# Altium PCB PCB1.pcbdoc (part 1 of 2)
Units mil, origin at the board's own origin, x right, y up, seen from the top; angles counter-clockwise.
Board outline 2817.44 x 1578.14 mil, 2 copper layers (Top Layer, Bottom Layer); 132 components, 113 nets, 538 pads, 285 vias.
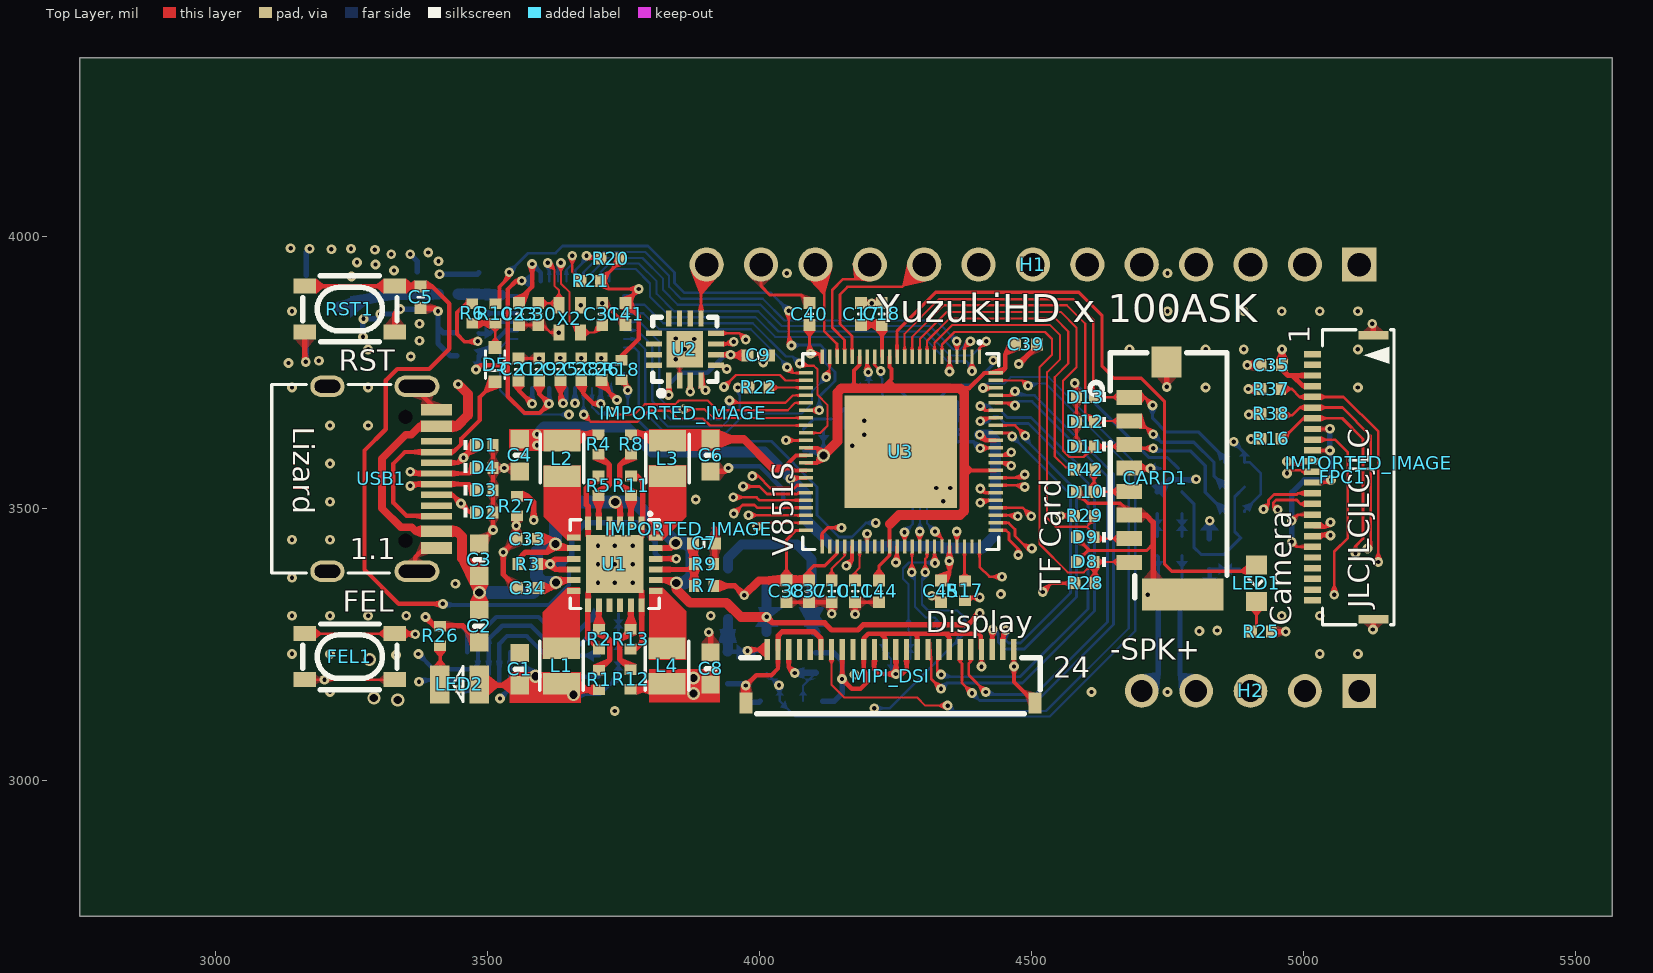
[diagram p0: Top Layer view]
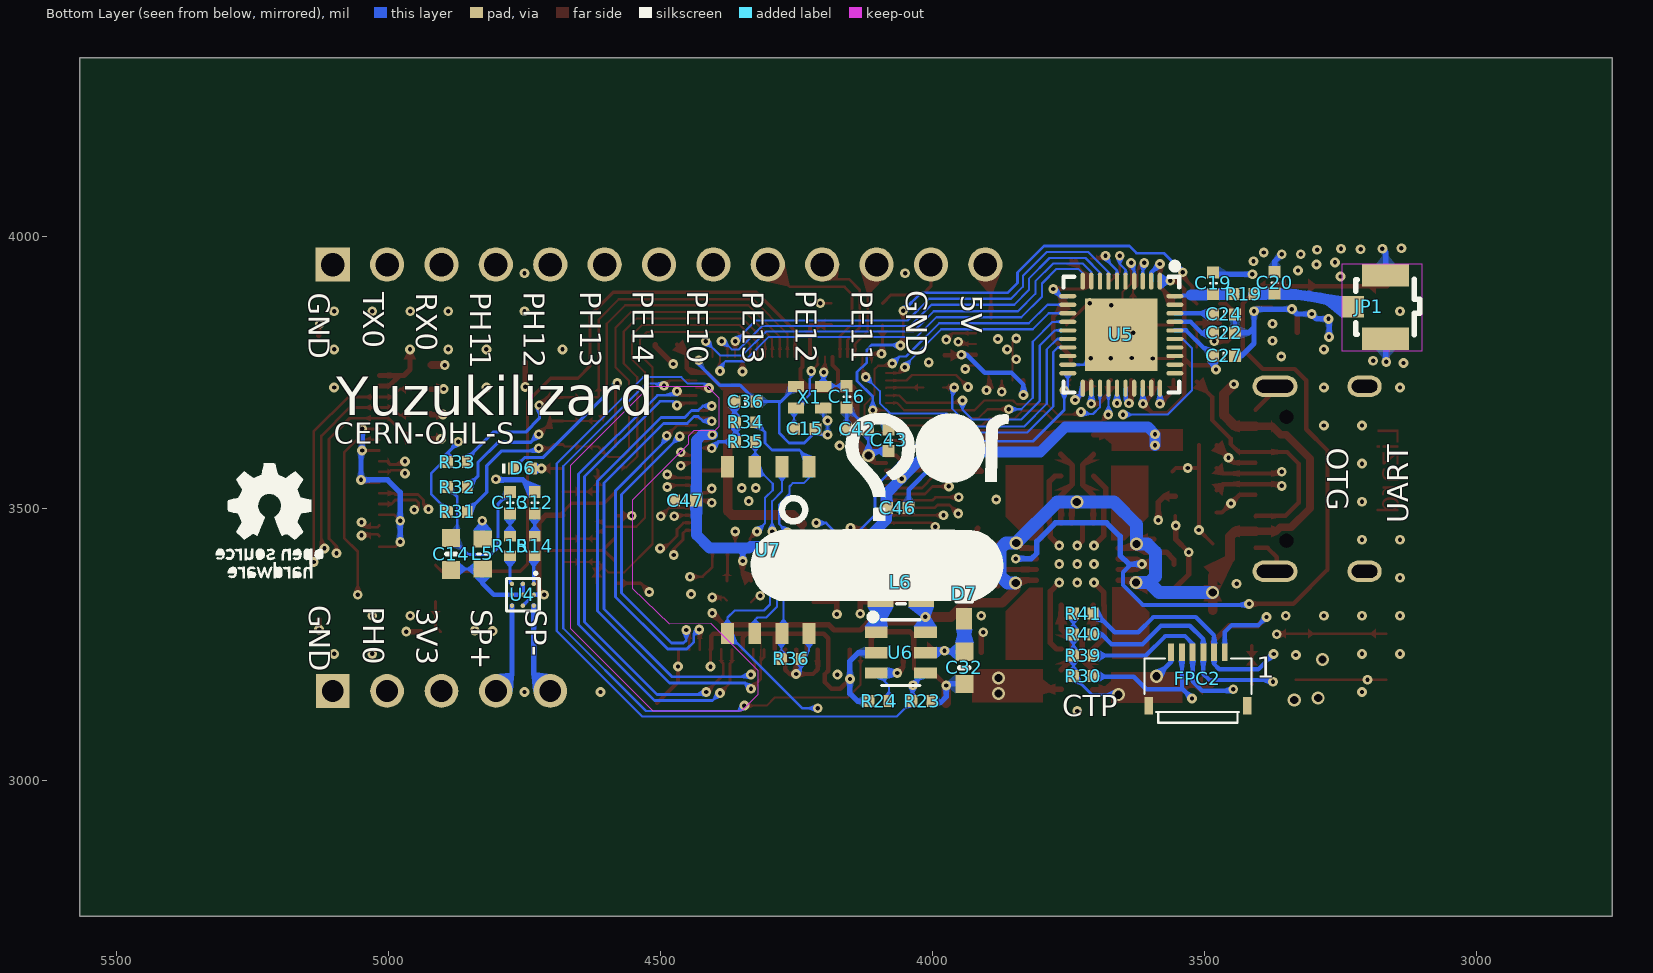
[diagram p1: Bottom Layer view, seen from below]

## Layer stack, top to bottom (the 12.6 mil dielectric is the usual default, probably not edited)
Top Solder: solder mask 0.4, Solder Resist, Dk 3.5
Top Layer: signal copper 1.4
Dielectric 1: dielectric 12.6, FR-4, Dk 4.8
Bottom Layer: signal copper 1.4
Bottom Solder: solder mask 0.4, Solder Resist, Dk 3.5

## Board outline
5567.44,2750 2750,2750 2750,4328.14 5567.44,4328.14

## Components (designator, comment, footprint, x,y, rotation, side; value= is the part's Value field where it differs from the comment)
C1 "CAP_0603" "C0603 NSK" 3558.67,3204.23 r270 top
C2 "CAP_0603" "C0603 NSK" 3484.5,3283.13 r90 top
C3 "CAP_0603" "C0603 NSK" 3484.5,3405.13 r270 top
C4 "CAP_0603" "C0603 NSK" 3558.67,3597.28 r90 top
C5 "100nF" C0402-NSK 3376.5,3888.14 r270 top
C6 "CAP_0603" "C0603 NSK" 3909.67,3597.28 r90 top
C7 "100nF" C0402-NSK 3897.67,3435.26 r180 top
C8 "CAP_0603" "C0603 NSK" 3909.67,3205.26 r270 top
C9 "100nF" C0402-NSK 3997.5,3781.13 r180 top
C10 "2.2uF" C0402-NSK 4132.5,3347.13 r270 top
C11 "470nF" C0402-NSK 4175.5,3347.13 r270 top
C12 "100nF" C0402-NSK 4731.05,3510.31 r270 bottom
C13 "100nF" C0402-NSK 4776.36,3510.31 r270 bottom
C14 "CAP_0603" "C0603 NSK" 4884.85,3415.88 r270 bottom
C15 "22pF" C0402-NSK 4234.5,3646.05 r180 bottom
C16 "22pF" C0402-NSK 4157.5,3705.05 r270 bottom
C17 "2.2uF" C0402-NSK 4186.3,3857.06 r270 top
C18 "100nF" C0402-NSK 4224.43,3857.34 r270 top
C19 "CAP_0402" C0402-NSK 3483.64,3913.49 r270 bottom
C20 "CAP_0402" C0402-NSK 3370.64,3914.49 r270 bottom
C21 "CAP_0402" C0402-NSK 3556.67,3755.24 r90 top
C22 "CAP_0402" C0402-NSK 3463.46,3822.36 r180 bottom
C23 "CAP_0402" C0402-NSK 3557.85,3856.99 r270 top
C24 "CAP_0402" C0402-NSK 3463.46,3856.36 r180 bottom
C25 "CAP_0402" C0402-NSK 3633.95,3755.7 r90 top
C26 "CAP_0402" C0402-NSK 3708.95,3755.7 r90 top
C27 "CAP_0402" C0402-NSK 3463.5,3780.13 r180 bottom
C28 "CAP_0402" C0402-NSK 3671.95,3755.7 r90 top
C29 "CAP_0402" C0402-NSK 3594.67,3755.24 r90 top
C30 "22pF" C0402-NSK 3592.85,3857 r270 top
C31 "22pF" C0402-NSK 3710.5,3857.13 r90 top
C32 "CAP_0603" "C0603 NSK" 3940.92,3206.54 r90 bottom
C33 "1uF" C0402-NSK 3572.67,3443.26 r180 top
C34 "1uF" C0402-NSK 3573.67,3353.26 r180 top
C35 "100nF" C0402-NSK 4940.5,3763.13 r0 top
C36 "100nF" C0402-NSK 4343.5,3696.13 r0 bottom
C37 "100nF" C0402-NSK 4090.5,3347.13 r90 top
C38 "100nF" C0402-NSK 4049.5,3347.13 r90 top
C39 "100nF" C0402-NSK 4489.5,3801.13 r0 top
C40 "100nF" C0402-NSK 4091.5,3857.13 r270 top
C41 "100nF" C0402-NSK 3753.5,3857.13 r90 top
C42 "100nF" C0402-NSK 4138.5,3645.13 r180 bottom
C43 "100nF" C0402-NSK 4080.5,3625.13 r270 bottom
C44 "100nF" C0402-NSK 4219.5,3347.13 r90 top
C45 "100nF" C0402-NSK 4333.5,3347.13 r90 top
C46 "100nF" C0402-NSK 4063.5,3500.13 r0 bottom
C47 "100nF" C0402-NSK 4454.5,3514.13 r180 bottom
CARD1 "TF-021B-H265" TF-SMD_TF-021B-H265 4728.5,3555.13 r90 top
D1 "0402ESDA-05N" D0402 3493.5,3616.13 r0 top
D2 "0402ESDA-05N" D0402 3493.5,3492.13 r0 top
D3 "0402ESDA-05N" D0402 3493.5,3533.13 r0 top
D4 "0402ESDA-05N" D0402 3493.5,3574.13 r0 top
D5 "1N5819-SOD523" SOD-523_L1.2-W0.8-LS1.6-FD 3513.5,3764.13 r270 top
D6 "0402ESDA-05N" D0402 4753.5,3573.13 r180 bottom
D7 "B5819WS_C22624" SOD-323_L1.8-W1.3-LS2.5-RD 3941.5,3343.13 r90 bottom
D8 "0402ESDA-05N" D0402 4598.84,3401.36 r180 top
D9 "0402ESDA-05N" D0402 4598.84,3446.73 r180 top
D10 "0402ESDA-05N" D0402 4598.5,3530.13 r180 top
D11 "0402ESDA-05N" D0402 4598.84,3613.47 r180 top
D12 "0402ESDA-05N" D0402 4598.84,3658.84 r180 top
D13 "0402ESDA-05N" D0402 4598.84,3704.21 r180 top
FEL1 "PTS810SJM250SMTRLFS" KEY-SMD_4P-L4.2-W3.2-P2.20-LS4.6 3246.5,3227.13 r0 top
FPC1 "F0502-B-24-10G-R" FPC-SMD_F0502-B-24-10G-R 5072.5,3557.13 r90 top
FPC2 "FH19C-6S-0.5SH(10)" FPC-SMD_FH19C-6S-0.5SH 3511.5,3186.13 r180 bottom
H1 "HDR-F_2.54_1x13P" HDR-TH_13P-P2.54-V-F 4502.5,3948.13 r180 top
H2 "HDR-F_2.54_1x5P" HDR-TH_5P-P2.54-V-F 4902.5,3164.13 r180 top
IMPORTED_IMAGE "IMPORTED_IMAGE" IMPORTED_IMAGE 3859.5,3675.13 r0 top
IMPORTED_IMAGE "IMPORTED_IMAGE" IMPORTED_IMAGE 3869.57,3461.13 r0 top
IMPORTED_IMAGE "IMPORTED_IMAGE" IMPORTED_IMAGE 5119.5,3583.13 r0 top
JP1 "U.FL-R-SMT-1(80)" RF-SMD_FRF05002-JSS103M 3196.5,3870.13 r270 bottom
L1 "2.2uH" IND-SMD_L2.0-W1.6 3635.67,3210.26 r270 top
L2 "2.2uH" IND-SMD_L2.0-W1.6 3636.67,3591.26 r90 top
L3 "2.2uH" IND-SMD_L2.0-W1.6 3830.67,3591.26 r90 top
L4 "2.2uH" IND-SMD_L2.0-W1.6 3829.67,3210.26 r270 top
L5 "UPZ1608E101-3R0TF" "L0603 NSK" 4826.85,3415.88 r90 bottom
L6 "WPN252012H4R7MT" IND-SMD_L2.5-W2.0_SWPA252010S1R0MT 4057.92,3363.54 r0 bottom
LED1 "LED_0603-R" "LED0603 NSK" 4913.5,3362.13 r90 top
LED2 "LED_0807-RGB" RGBLED_0807 3448.5,3176.13 r180 top
MIPI_DSI "FH34SRJ-24S-0.5SH(50)" FFC-SMD_24P-P0.50_FH34SRJ-24S-0.5SH 4240.5,3191.13 r0 top
R1 "680K" R0402-NSK_2 3704.67,3184.26 r270 top
R2 "150K" R0402-NSK_2 3704.67,3259.26 r270 top
R3 "10K" R0402-NSK_2 3573.67,3397.26 r180 top
R4 "300K" R0402-NSK_2 3703.67,3617.26 r90 top
R5 "150K" R0402-NSK_2 3703.67,3541.26 r90 top
R6 "Res_0402" R0402-NSK_2 3471.5,3858.13 r90 top
R7 "100K" R0402-NSK_2 3897.67,3357.26 r0 top
R8 "150K" R0402-NSK_2 3763.67,3617.26 r90 top
R9 "100K" R0402-NSK_2 3897.67,3397.26 r180 top
R10 "Res_0402" R0402-NSK_2 3513.83,3857.92 r270 top
R11 "100K" R0402-NSK_2 3763.67,3541.26 r90 top
R12 "75K" R0402-NSK_2 3762.67,3185.26 r270 top
R13 "150K" R0402-NSK_2 3762.67,3259.26 r270 top
R14 "100K" R0402-NSK_2 4731.05,3430.47 r270 bottom
R15 "100K" R0402-NSK_2 4776.36,3430.47 r270 bottom
R16 "2K" R0402-NSK_2 4940.34,3627.81 r0 top
R17 "33" R0402-NSK_2 4377.5,3348.13 r270 top
R18 "47K" R0402-NSK_2 3745.67,3754.24 r90 top
R19 "Res_0402" R0402-NSK_2 3427.25,3893.8 r180 bottom
R20 "47K" R0402-NSK_2 3726.5,3959.13 r0 top
R21 "47K" R0402-NSK_2 3689.5,3918.13 r0 top
R22 "33" R0402-NSK_2 3998.5,3722.13 r0 top
R23 "Res_0402" R0402-NSK_2 4018.92,3145.54 r0 bottom
R24 "Res_0402" R0402-NSK_2 4097.92,3145.53 r180 bottom
R25 "2K" R0402-NSK_2 4922.5,3273.13 r0 top
R26 "2K" R0402-NSK_2 3412.5,3265.13 r90 top
R27 "100K" R0402-NSK_2 3553.5,3504.13 r90 top
R28 "47K" R0402-NSK_2 4598.5,3362.13 r180 top
R29 "47K" R0402-NSK_2 4597.5,3486.13 r180 top
R30 "10K" R0402-NSK_2 3722.5,3191.13 r180 bottom
R31 "47K" R0402-NSK_2 4873.34,3493.31 r0 bottom
R32 "47K" R0402-NSK_2 4873.34,3539 r0 bottom
R33 "47K" R0402-NSK_2 4873.34,3584.68 r0 bottom
R34 "Res_0402" R0402-NSK_2 4343.5,3658.13 r0 bottom
R35 "Res_0402" R0402-NSK_2 4343.5,3622.14 r0 bottom
R36 "Res_0402" R0402-NSK_2 4259.5,3223.13 r180 bottom
R37 "10K" R0402-NSK_2 4940.34,3719.18 r0 top
R38 "2K" R0402-NSK_2 4940.34,3673.49 r0 top
R39 "2K" R0402-NSK_2 3722.5,3229.13 r180 bottom
R40 "2K" R0402-NSK_2 3722.5,3268.13 r180 bottom
R41 "10K" R0402-NSK_2 3722.5,3306.13 r180 bottom
R42 "33" R0402-NSK_2 4598.5,3571.13 r0 top
RST1 "PTS810SJM250SMTRLFS" KEY-SMD_4P-L4.2-W3.2-P2.20-LS4.6 3246.5,3866.13 r180 top
U1 "EA3059" QFN-24_L4.0-W4.0-P0.50-TL-EP2.7 3733.67,3397.26 r270 top
U2 "CH343P" TQFN-16_L3.0-W3.0-P0.50-BL-EP1.7 3862.5,3792.13 r0 top
U3 "V851S" QFN-88_L9.0-W9.0-P0.35-BL-EP5.26 4259.5,3604.13 r180 top
U4 "AW8010AFCR" FC-9_L1.5-W1.5-R3-C3-P0.50-BL 4752.85,3340.88 r0 bottom
U5 "XR829" QFN-40_L5.0-W5.0-P0.40-BL-EP3.4 3652.5,3819.13 r0 bottom
U6 "RY3730" SOT-23-6_L2.9-W1.6-P0.95-LS2.8-BL 4057.92,3234.54 r270 bottom
U7 "W25Q128JVSIQ" SOIC-8_L5.3-W5.3-P1.27-LS8.0-BL_1 4301.5,3428.13 r0 bottom
USB1 "TYPEC-304-BCP16" USB-C-SMD_TYPEC-304-BCP16-1 3305.5,3554.13 r270 top
X1 "24MHz" OSC-SMD_4P-L2.0-W1.6-BL 4225.5,3704.05 r0 bottom
X2 "40MHz" OSC-SMD_4P-L2.0-W1.6-BL 3650.85,3847.99 r270 top

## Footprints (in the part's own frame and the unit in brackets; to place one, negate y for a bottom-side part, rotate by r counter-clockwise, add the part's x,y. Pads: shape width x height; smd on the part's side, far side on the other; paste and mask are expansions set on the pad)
C0402-NSK [mil]
  rect 22x22 smd: 1(-19.99,0) 2(20.01,0)
  silkscreen extent 0,-5 0,6
"C0603 NSK" [mm]
  rect 0.85x0.85 smd: 1(-0.75,0) 2(0.75,0)
  silkscreen extent 0,-0.21 0,0.21
D0402 [mil]
  rect 19.89x21.68 smd: 1(-16.4,0) 2(16.4,0)
  silkscreen extent -37,-9 -31,9
FC-9_L1.5-W1.5-R3-C3-P0.50-BL [mil]
  round 8.19 smd: A1(-20,-20) A2(-20,0) A3(-20,20) B1(0,-20) B2(0,0) B3(0,20) C1(20,-20) C2(20,0) C3(20,20)
  silkscreen extent -30,-41 30,30
FFC-SMD_24P-P0.50_FH34SRJ-24S-0.5SH [mil]
  rect 9.8x39.4 smd: 1(226.4,49.2) 2(206.7,49.2) 3(187,49.2) 4(167.3,49.2) 5(147.6,49.2) 6(128,49.2) 7(108.3,49.2) 8(88.6,49.2) 9(68.9,49.2) 10(49.2,49.2) 11(29.5,49.2) 12(9.9,49.2) 13(-9.8,49.2) 14(-29.5,49.2) 15(-49.2,49.2) 16(-68.9,49.2) 17(-88.6,49.2) 18(-108.3,49.2) 19(-127.9,49.2) 20(-147.6,49.2) 21(-167.3,49.2) 22(-187,49.2) 23(-206.7,49.2) 24(-226.4,49.2)
  rect 23.6x39.4 smd: 25(-265.7,-49.2) 26(265.8,-49.2)
  silkscreen extent -276,-69 276,34
FPC-SMD_F0502-B-24-10G-R [mm]
  rect 0.3x0.8 smd: 1(5.75,1.418) 2(5.25,1.418) 3(4.75,1.418) 4(4.25,1.418) 5(3.75,1.418) 6(3.25,1.418) 7(2.75,1.418) 8(2.25,1.418) 9(1.75,1.418) 10(1.25,1.418) 11(0.75,1.418) 12(0.25,1.418) 13(-0.25,1.418) 14(-0.75,1.418) 15(-1.25,1.418) 16(-1.75,1.418) 17(-2.25,1.418) 18(-2.75,1.418) 19(-3.25,1.418) 20(-3.75,1.418) 21(-4.25,1.418) 22(-4.75,1.418) 23(-5.25,1.418) 24(-5.75,1.418)
  rect 0.4x1.4 smd: 25(-6.635,-1.418) 26(6.635,-1.418)
  silkscreen extent -6.89,-2.39 6.89,0.96
FPC-SMD_FH19C-6S-0.5SH [mil]
  rect 11x31.5 smd: 1(-49.2,49.2) 2(-29.5,49.2) 3(-9.9,49.2) 4(9.8,49.2) 5(29.5,49.2) 6(49.2,49.2)
  rect 15.7x31.5 smd: 7(90.6,-49.2) 8(-90.6,-49.2)
  silkscreen extent -98,-81 98,37
HDR-TH_5P-P2.54-V-F [mil]
  rect 62x62 hole 40.16: 1(-200,0)
  round 62 hole 40.16: 2(-100,0) 3(0,0) 4(100,0) 5(200,0)
HDR-TH_13P-P2.54-V-F [mil]
  rect 63x63 hole 43.3: 1(-600,0)
  round 63 hole 43.3: 2(-500,0) 3(-400,0) 4(-300,0) 5(-200,0) 6(-100,0) 7(0,0) 8(100,0) 9(200,0) 10(300,0) 11(400,0) 12(500,0) 13(600,0)
IMPORTED_IMAGE [mil]
IND-SMD_L2.0-W1.6 [mm]
  rect 1x1.72 smd: 1(0.828,0) 2(-0.828,0)
  silkscreen extent -1.14,-1.02 1.14,1.02
IND-SMD_L2.5-W2.0_SWPA252010S1R0MT [mil]
  rect 47.2x90.6 smd: 1(-37.4,0) 2(37.4,0)
  silkscreen extent -8,-40 8,39
KEY-SMD_4P-L4.2-W3.2-P2.20-LS4.6 [mil]
  rect 41.3x27.6 smd: 1(-82.7,42.3) 2(82.7,42.3) 3(-82.7,-42.3) 4(82.7,-42.3)
  silkscreen extent -87,-61 87,60
"L0603 NSK" [mm]
  rect 0.8x0.864 smd: 1(0.7,0) 2(-0.7,0)
  silkscreen extent 0,-0.25 0,0.24
"LED0603 NSK" [mm]
  rect 0.9x1 smd: 1(-0.85,0) 2(0.85,0)
  silkscreen extent -0.17,-0.36 0.2,0.37
OSC-SMD_4P-L2.0-W1.6-BL [mil]
  rect 30x20 smd: 1(-25,-20) 2(25,-20) 3(25,20) 4(-25,20)
QFN-24_L4.0-W4.0-P0.50-TL-EP2.7 [mm]
  rect 0.633x0.28 smd: 1(-1.912,1.25) 2(-1.912,0.75) 3(-1.912,0.25) 4(-1.912,-0.25) 5(-1.912,-0.75) 6(-1.912,-1.25) 13(1.912,-1.25) 14(1.912,-0.75) 15(1.912,-0.25) 16(1.912,0.25) 17(1.912,0.75) 18(1.912,1.25)
  rect 0.28x0.633 smd: 7(-1.25,-1.912) 8(-0.75,-1.912) 9(-0.25,-1.912) 10(0.25,-1.912) 11(0.75,-1.912) 12(1.25,-1.912) 19(1.25,1.912) 20(0.75,1.912) 21(0.25,1.912) 22(-0.25,1.912) 23(-0.75,1.912) 24(-1.25,1.912)
  rect 2.7x2.7 smd: 25(0,0)
  silkscreen extent -2.42,-2.08 2.08,2.08
QFN-40_L5.0-W5.0-P0.40-BL-EP3.4 [mm]
  oval 0.2x0.8 smd: 1(-1.8,-2.499) 2(-1.4,-2.499) 3(-1,-2.499) 4(-0.6,-2.499) 5(-0.2,-2.499) 6(0.2,-2.499) 7(0.6,-2.499) 8(1,-2.499) 9(1.4,-2.499) 10(1.8,-2.499) 21(1.8,2.499) 22(1.4,2.499) 23(1,2.499) 24(0.6,2.499) 25(0.2,2.499) 26(-0.2,2.499) 27(-0.6,2.499) 28(-1,2.499) 29(-1.4,2.499) 30(-1.8,2.499)
  oval 0.8x0.2 smd: 11(2.499,-1.8) 12(2.499,-1.4) 13(2.499,-1) 14(2.499,-0.6) 15(2.499,-0.2) 16(2.499,0.2) 17(2.499,0.6) 18(2.499,1) 19(2.499,1.4) 20(2.499,1.8) 31(-2.499,1.8) 32(-2.499,1.4) 33(-2.499,1) 34(-2.499,0.6) 35(-2.499,0.2) 36(-2.499,-0.2) 37(-2.499,-0.6) 38(-2.499,-1) 39(-2.499,-1.4) 40(-2.499,-1.8)
  rect 3.4x3.4 smd: 41(0,0)
  silkscreen extent -2.7,-3.35 2.7,2.7
QFN-88_L9.0-W9.0-P0.35-BL-EP5.26 [mm]
  rect 0.16x0.665 smd: 1(-3.675,-4.433) 2(-3.325,-4.433) 3(-2.975,-4.433) 4(-2.625,-4.433) 5(-2.275,-4.433) 6(-1.925,-4.433) 7(-1.575,-4.433) 8(-1.225,-4.433) 9(-0.875,-4.433) 10(-0.525,-4.433) 11(-0.175,-4.433) 12(0.175,-4.433) 13(0.525,-4.433) 14(0.875,-4.433) 15(1.225,-4.433) 16(1.575,-4.433) 17(1.925,-4.433) 18(2.275,-4.433) 19(2.625,-4.433) 20(2.975,-4.433) 21(3.325,-4.433) 22(3.675,-4.433) 45(3.675,4.433) 46(3.325,4.433) 47(2.975,4.433) 48(2.625,4.433) 49(2.275,4.433) 50(1.925,4.433) 51(1.575,4.433) 52(1.225,4.433) 53(0.875,4.433) 54(0.525,4.433) 55(0.175,4.433) 56(-0.175,4.433) 57(-0.525,4.433) 58(-0.875,4.433) 59(-1.225,4.433) 60(-1.575,4.433) 61(-1.925,4.433) 62(-2.275,4.433) 63(-2.625,4.433) 64(-2.975,4.433) 65(-3.325,4.433) 66(-3.675,4.433)
  rect 0.665x0.16 smd: 23(4.433,-3.675) 24(4.433,-3.325) 25(4.433,-2.975) 26(4.433,-2.625) 27(4.433,-2.275) 28(4.433,-1.925) 29(4.433,-1.575) 30(4.433,-1.225) 31(4.433,-0.875) 32(4.433,-0.525) 33(4.433,-0.175) 34(4.433,0.175) 35(4.433,0.525) 36(4.433,0.875) 37(4.433,1.225) 38(4.433,1.575) 39(4.433,1.925) 40(4.433,2.275) 41(4.433,2.625) 42(4.433,2.975) 43(4.433,3.325) 44(4.433,3.675) 67(-4.433,3.675) 68(-4.433,3.325) 69(-4.433,2.975) 70(-4.433,2.625) 71(-4.433,2.275) 72(-4.433,1.925) 73(-4.433,1.575) 74(-4.433,1.225) 75(-4.433,0.875) 76(-4.433,0.525) 77(-4.433,0.175) 78(-4.433,-0.175) 79(-4.433,-0.525) 80(-4.433,-0.875) 81(-4.433,-1.225) 82(-4.433,-1.575) 83(-4.433,-1.925) 84(-4.433,-2.275) 85(-4.433,-2.625) 86(-4.433,-2.975) 87(-4.433,-3.325) 88(-4.433,-3.675)
  rect 5.26x5.26 smd: 89(0,0)
  silkscreen extent -4.58,-5.17 4.58,4.58
R0402-NSK_2 [mil]
  rect 19.68x22 smd: 1(-18,0) 2(18,0)
RF-SMD_FRF05002-JSS103M [mm]
  rect 1x1.05 smd: 1(0,-0.762)
  rect 1.05x2.2 smd: 2(-1.475,0.762) 3(1.475,0.762)
  silkscreen extent -1.3,-0.63 1.3,2.35
RGBLED_0807 [mil]
  rect 35.83x70 smd: 1(-36,0) 2(37,0)
  silkscreen extent -6,-33 12,32
SOD-323_L1.8-W1.3-LS2.5-RD [mil]
  rect 39.4x29.5 smd: 1(-46.2,0) 2(46.2,0)
  silkscreen extent -15,-15 -15,15
SOD-523_L1.2-W0.8-LS1.6-FD [mil]
  rect 23.6x23.6 smd: 1(-31.5,0) 2(31.5,0)
  silkscreen extent -26,-18 26,18
SOIC-8_L5.3-W5.3-P1.27-LS8.0-BL_1 [mil]
  rect 23.6x39.4 smd: 1(-75,-148.5) 2(-25,-148.5) 3(25,-148.5) 4(75,-148.5) 5(75,158.5) 6(25,158.5) 7(-25,158.5) 8(-75,158.5)
  silkscreen extent -68,-90 -25,-48
SOT-23-6_L2.9-W1.6-P0.95-LS2.8-BL [mil]
  rect 20.9x42.2 smd: 1(-37.4,-45.2) 2(0,-45.2) 3(37.4,-45.2) 4(37.4,45.2) 5(0,45.2) 6(-37.4,45.2)
  silkscreen extent -72,-57 61,35
TF-SMD_TF-021B-H265 [mil]
  rect 27.6x47.2 smd: 1(148.6,49.2) 2(105.3,49.2) 3(62,49.2) 4(18.7,49.2) 5(-24.6,49.2) 6(-67.9,49.2) 7(-111.2,49.2) 8(-154.5,49.2)
  rect 59.1x149.6 smd: 9(-213.6,-49.2)
  rect 57.1x55.1 smd: 10(213.6,-19.7)
  silkscreen extent -220,-131 230,121
TQFN-16_L3.0-W3.0-P0.50-BL-EP1.7 [mm]
  rect 0.25x0.75 smd: 1(-0.748,-1.45) 2(-0.249,-1.45) 3(0.252,-1.45) 4(0.751,-1.45) 9(0.75,1.45) 10(0.25,1.45) 11(-0.25,1.45) 12(-0.749,1.45)
  rect 0.75x0.25 smd: 5(1.45,-0.75) 6(1.45,-0.25) 7(1.45,0.25) 8(1.45,0.75) 13(-1.45,0.75) 14(-1.45,0.25) 15(-1.45,-0.25) 16(-1.45,-0.75)
  rect 1.7x1.7 smd: 17(0,0)
  silkscreen extent -1.5,-2.17 1.5,1.5
USB-C-SMD_TYPEC-304-BCP16-1 [mil]
  oval 39.4x82.7 hole 23.6 slot 66.9 at 90 deg: 12(-170.1,64.3) 13(170.1,64.3)
  oval 39.4x63 hole 23.6 slot 47.2 at 90 deg: 14(-170.1,-100.3) 15(170.1,-100.3)
  rect 21.7x57.1 smd: A1B12(-127,100.3) A4B9(-96.5,100.3) B1A12(127,100.3) B4A9(96.5,100.3)
  rect 11.8x57.1 smd: A5(-49.2,100.3) A6(-9.8,100.3) A7(9.8,100.3) A8(49.2,100.3) B5(68.9,100.3) B6(29.5,100.3) B7(-29.5,100.3) B8(-68.9,100.3)
  Multi-Layer board cut-out: -113.8,56.2 -119.35,54.93 -123.81,51.38 -126.28,46.25 -126.28,40.55 -123.81,35.42 -119.35,31.87 -113.8,30.6 -113.8,30.6 -108.25,31.87 -103.79,35.42 -101.32,40.55 -101.32,46.25 -103.79,51.38 -108.25,54.93 -113.8,56.2
  Multi-Layer board cut-out: 113.8,56.2 108.25,54.93 103.79,51.38 101.32,46.25 101.32,40.55 103.79,35.42 108.25,31.87 113.8,30.6 113.8,30.6 119.35,31.87 123.81,35.42 126.28,40.55 126.28,46.25 123.81,51.38 119.35,54.93 113.8,56.2
  silkscreen extent -173,-203 173,16

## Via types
v1: diameter 18, hole 8, Top Layer to Bottom Layer, 271 vias
v2: diameter 24, hole 15, Top Layer to Bottom Layer, 14 vias

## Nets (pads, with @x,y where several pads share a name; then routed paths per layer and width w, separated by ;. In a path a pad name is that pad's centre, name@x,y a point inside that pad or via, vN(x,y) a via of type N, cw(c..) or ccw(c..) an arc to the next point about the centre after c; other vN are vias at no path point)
0V9: C8.2 C39.1 C42.2 C43.2 C44.2 L4.1 R12.2 U3.13 U3.17 U3.33 U3.35 U3.54 U3.75 U3.88 | length 2081.4
  Top Layer w6: C44.2@4219.5,3367.14 4219.5,3394.13 4238.83,3413.46 U3.54@4238.83,3429.62
  Top Layer w7: U3.35@4084.99,3583.46 4085.32,3583.13 4105.5,3583.13 4113.5,3591.13 4113.5,3604.13 4106.61,3611.02 U3.33@4084.99,3611.02 ; 4164.62,3720.68 4173.5,3729.56 ; 4182.38,3720.68 4173.5,3729.56 ; U3.17@4183.71,3778.64 4183.71,3763.34 4173.5,3753.13 4173.5,3729.56 ; 4225.49,3720.68 4238.83,3734.01 ; U3.54@4238.83,3429.62 4238.83,3470.46 ; U3.13@4238.83,3778.64 4238.83,3759.8 4242.5,3756.13 4242.5,3737.68 4238.83,3734.01 ; 4252.17,3720.68 4238.83,3734.01 ; 4376.04,3558.02 4387.71,3569.68 4389.81,3569.68 ; 4376.04,3583.45 4389.81,3569.68 ; U3.75@4434.01,3569.68 4389.81,3569.68
  Top Layer w8: 4368.43,3720.68 4385.04,3720.68 4413.19,3748.82 4443.19,3748.82 4451.5,3757.13 4451.5,3783.13 C39.1@4469.51,3801.13
  Top Layer w10: R12.2@3762.67,3167.25 3819.27,3167.25 L4.1@3829.67,3177.66
  Top Layer w18: v2(4117.5,3597.13) 4142.96,3622.59 4142.96,3713.06 4150.57,3720.68 4164.62,3720.68 4182.38,3720.68 4225.49,3720.68 4252.17,3720.68 4368.43,3720.68 4376.04,3713.06 4376.04,3583.45 4376.04,3558.02 4376.04,3495.21 4368.43,3487.59 4255.96,3487.59 4239.5,3471.13
  Mid-Layer 1 w23: v2(3878.5,3159.13) v2(3878.5,3188.13) 3878.5,3376.13 3938.5,3436.13 4056.5,3436.13 4119.5,3499.13 4119.5,3595.13 v2(4117.5,3597.13)
  Bottom Layer w6: C43.2@4080.5,3605.13 4109.51,3605.13 v2(4117.5,3597.13) 4117.5,3644.14 C42.2@4118.49,3645.13
1V5: C6.2 L3.1 R8.2 U3.34 U3.36 | length 323.2
  Top Layer w7: U3.36@4084.99,3569.68 4064.28,3569.68 4060.83,3573.13 4042.5,3573.13 4066.5,3597.13 4084.88,3597.13 U3.34@4084.99,3597.24
  Top Layer w10: R8.2@3763.67,3635.26 3819.27,3635.26 L3.1@3830.67,3623.86
  Top Layer w15: C6.2@3909.67,3626.81 3970.83,3626.81 4024.5,3573.13 4042.5,3573.13
1V8: C4.2 C45.2 C46.2 C47.2 L2.1 R4.2 R16.1 R37.1 R38.1 U3.37 U3.62 U3.79 | length 2127.8
  Top Layer w7: v1(4056.5,3554.13) 4058.27,3555.9 U3.37@4084.99,3555.9
  Top Layer w8: C45.2@4333.5,3367.14 4349.06,3382.7 v1@4349.06,3403.69 ; v1(4348.5,3403.13) v1@4349.06,3403.69 ; U3.62@4349.06,3429.62 v1@4349.06,3403.69 ; v1(4404.5,3635.13) 4414.83,3624.8 U3.79@4434.01,3624.8
  Top Layer w10: L2.1@3636.67,3623.86 3648.07,3635.26 R4.2@3703.67,3635.26 ; v1(4898.55,3719.18) R37.1@4922.34,3719.18 ; v1(4899.5,3672.13) 4920.98,3672.13 R38.1@4922.34,3673.5 ; v1(4903.5,3627.13) 4921.66,3627.13 R16.1@4922.34,3627.81
  Mid-Layer 2 w15: v1(4404.5,3635.13) 4419.5,3635.13 4443.5,3659.13 4886.5,3659.13 v1(4899.5,3672.13) ; v1(4898.55,3719.18) 4899.5,3718.23 v1(4899.5,3672.13) ; v1(4903.5,3627.13) 4903.5,3668.13 v1(4899.5,3672.13)
  Bottom Layer w8: 4336.87,3427.13 4348.5,3415.5 4348.5,3415.15 ; v1(4348.5,3403.13) 4348.5,3415.15 ; 4360.49,3427.13 4348.5,3415.15
  Bottom Layer w20: v1(3590.5,3615.67) v1(3590.5,3636.13) 3603.5,3649.13 3755.5,3649.13 3801.5,3603.13 4008.5,3603.13 v1@4057.5,3554.13 ; v1(4056.5,3554.13) v1@4057.5,3554.13 ; v1(4404.5,3635.13) 4423.17,3635.13 4433.5,3624.8 4433.5,3451.13 4409.5,3427.13 4381.5,3427.13 4360.49,3427.13 4336.87,3427.13 4333.88,3430.12 4133.51,3430.12 4084.5,3479.13 4084.5,3527.13 v1@4057.5,3554.13
3V3: C1.2 C21.1 C22.1 C35.2 C36.2 C37.2 C38.2 C40.2 C41.2 CARD1.4 D6.2 FPC1.3 FPC1.4 FPC2.1 H2.3 L1.1 LED2.1 MIPI_DSI.11 MIPI_DSI.12 MIPI_DSI.14 R1.2 R6.2 R7.2 R18.2 R20.2 R21.2 R28.2 R29.2 R30.1 R31.2 R33.2 R34.2 R35.2 R36.2 R39.1 R40.1 R41.1 U3.5 U3.22 U3.44 U3.47 U3.55 U3.78 U5.11 U5.25 U5.30 U5.37 U7.8 | length 2588.9
  Top Layer w4: v1(4405.5,3610.13) 4406.39,3611.02 U3.78@4434.01,3611.02
  Top Layer w5: v1(4093.5,3784.13) 4109.32,3784.13 U3.22@4114.81,3778.64
  Top Layer w6: R20.2@3744.5,3959.14 3744.5,3955.14 R21.2@3707.5,3918.14 3722.51,3903.13 v1(3777.5,3903.13) 3753.5,3879.13 C41.2@3753.5,3877.14 ; C38.2@4049.5,3367.14 4049.5,3442.13 4066.5,3459.13 4084.67,3459.13 U3.44@4084.99,3459.45 ; C37.2@4090.5,3367.14 4090.5,3385.13 4099.5,3394.13 4119.5,3394.13 4142.37,3417 U3.47@4142.37,3429.62 ; C40.2@4091.5,3837.13 4091.5,3786.13 v1(4093.5,3784.13) ; v1(4520.5,3346.13) 4536.5,3362.13 R28.2@4580.5,3362.13 ; v1(4552.5,3486.13) R29.2@4579.5,3486.13 ; CARD1.4@4679.3,3573.83 4680,3573.13 v1(4718.5,3573.13)
  Top Layer w7: R6.2@3471.5,3876.13 3459.5,3876.13 3443.5,3860.13 3443.5,3820.13 3457.5,3806.13 3480.5,3806.13 v1(3481.5,3807.13) ; v1(4250.5,3400.13) 4252.61,3402.24 U3.55@4252.61,3429.62 ; U3.5@4349.07,3778.64 v1(4349.07,3751.56) v1@4349.5,3751.13
  Top Layer w8: C21.1@3556.67,3735.24 3556.67,3716.96 v1(3581.5,3692.13) ; R18.2@3745.67,3772.24 3745.67,3779.3 3777.5,3811.13 3777.5,3853.14 C41.2@3753.5,3877.14 ; MIPI_DSI.14@4211,3240.33 4210.5,3239.83 4210.5,3204.13 4219.4,3195.23 v1(4250.4,3195.23) ; MIPI_DSI.12@4250.4,3240.33 v1(4250.4,3195.23) ; v1@4250.5,3195.13 v1(4250.4,3195.23) ; MIPI_DSI.11@4270,3240.33 4270.5,3239.83 4270.5,3203.13 4262.6,3195.23 v1(4250.4,3195.23)
  Top Layer w9: v1(4960.5,3792.13) 4960.5,3755.14 4971.51,3744.13 4979.79,3744.13 ; FPC1.4@5016.7,3724.43 4999.49,3724.43 4979.79,3744.13 ; FPC1.3@5016.69,3744.14 4979.79,3744.13
  Top Layer w10: LED2.1@3484.5,3176.13 3485.93,3174.7 C1.2@3558.67,3174.7 ; L1.1@3635.67,3177.66 3647.07,3166.25 R1.2@3704.67,3166.25 ; R7.2@3915.67,3357.26 3954.37,3357.26 v1(3971.5,3340.13)
  Top Layer w15: v1(3971.5,3340.13) 3998.51,3367.14 C38.2@4049.5,3367.14 C37.2@4090.5,3367.14
  Mid-Layer 1 w10: v1(3581.5,3692.13) 3609.5,3720.13 3645.5,3720.13 3660.5,3705.13 v1(3660.5,3693.13)
  Bottom Layer w4: U7.8@4226.5,3269.63 4226.5,3238.13 R36.2@4241.5,3223.14 4241.5,3204.13 v1(4250.4,3195.23)
  Bottom Layer w5: v2(3657.5,3157.13) 3706.49,3157.13 R30.1@3740.5,3191.14 R39.1@3740.5,3229.14 R40.1@3740.5,3268.14 R41.1@3740.5,3306.14 ; R31.2@4891.34,3493.31 4891.34,3495.97 4921.5,3526.13 4921.5,3564.13 4900.95,3584.68 R33.2@4891.34,3584.68
  Bottom Layer w6: C36.2@4363.51,3696.13 4363.51,3660.13 R34.2@4361.5,3658.13 R35.2@4361.5,3622.13 4393.5,3622.13 v1(4405.5,3610.13) ; v1(4718.5,3573.13) D6.2@4737.1,3573.13 ; v1(4871.5,3622.13) 4891.34,3602.29 R33.2@4891.34,3584.68
  Bottom Layer w8: C22.1@3483.46,3822.36 3484.69,3821.13 3503.5,3821.13 3525.12,3842.75 U5.37@3554.1,3842.75 ; FPC2.1@3560.7,3235.33 3560.7,3217.93 v2(3587.5,3191.13) ; v1(3581.5,3692.13) 3581.63,3692.26 U5.30@3581.63,3720.73 ; U5.25@3660.37,3720.73 3660.5,3720.6 v1(3660.5,3693.13) ; U5.11@3750.9,3890 3764.37,3890 v1(3777.5,3903.13)
  other v1: 4174.5,3194.13 3660.5,3693.13
  other v2: 3334.5,3147.13 3290.5,3151.13 3282.5,3222.13
$1N7632: L1.2 U1.12
$1N7633: R1.1 R2.1 U1.14 | length 136.5
  Top Layer w10: U1.14@3704.14,3321.99 3704.14,3277.79 R2.1@3704.67,3277.25 3724.67,3257.25 3724.67,3222.25 R1.1@3704.67,3202.25
$1N8833: R4.1 R5.1 U1.5 | length 143.5
  Top Layer w10: R4.1@3703.67,3599.26 3723.67,3579.26 3723.67,3543.26 R5.1@3703.67,3523.26 3704.14,3522.78 U1.5@3704.14,3472.51
$1N8834: L2.2 U1.7
$1N9427: L3.2 U1.24
$1N9428: R8.1 R11.1 U1.2 | length 144.3
  Top Layer w10: U1.2@3763.2,3472.51 3763.67,3472.98 R11.1@3763.67,3523.26 3742.67,3544.25 3742.67,3578.26 R8.1@3763.67,3599.26
$1N9433: R12.1 R13.1 U1.17 | length 135.5
  Top Layer w10: R12.1@3762.67,3203.25 3742.67,3223.25 3742.67,3257.25 R13.1@3762.67,3277.25 3763.2,3277.78 U1.17@3763.2,3321.99
$1N9434: L4.2 U1.19
$1N18371: C7.2 R7.1 R9.2 U1.21 | length 153.6
  Top Layer w10: U1.21@3808.93,3387.41 3869.83,3387.41 R9.2@3879.67,3397.25 ; C7.2@3877.67,3435.26 3877.67,3399.26 R9.2@3879.67,3397.25 ; R7.1@3879.67,3357.26 R9.2@3879.67,3397.25
$1N18373: C5.1 R3.1 R27.2 RST1.3 RST1.4 U1.9 U1.10 U1.22 | length 1972.7
  Top Layer w8: RST1.4@3163.8,3908.43 RST1.3@3329.2,3908.43 3329.5,3908.13 C5.1@3376.5,3908.13 3397.5,3908.13 3429.5,3876.13 3429.5,3793.13 3392.5,3756.13 3333.54,3756.13 3312.5,3735.09 3312.5,3645.13 3273.5,3606.13 3273.5,3387.13 3336.5,3324.13 v1(3417.5,3324.13)
  Top Layer w10: R27.2@3553.5,3522.13 3573.5,3522.13 3584.5,3511.13 v1(3584.5,3478.13) ; R3.1@3591.67,3397.25 v1(3614.67,3397.25) ; U1.10@3658.41,3387.41 3624.51,3387.41 v1(3614.67,3397.25) ; U1.9@3658.41,3407.09 3657.57,3406.26 3623.67,3406.26 v1(3614.67,3397.25) ; U1.22@3808.93,3407.09 3846.51,3407.09 v1(3846.67,3407.26)
  Mid-Layer 1 w10: v1(3584.5,3478.13) 3584.5,3427.42 v1(3614.67,3397.25)
  Bottom Layer w8: v1(3417.5,3324.13) 3419.5,3322.13 3612.83,3322.13 3649.5,3358.8 3649.5,3382.13 3634.38,3397.25
  Bottom Layer w10: v1(3614.67,3397.25) 3634.38,3397.25 3638.67,3397.25 3654.67,3413.26 3654.67,3448.26 3679.67,3473.26 3773.67,3473.26 3807.67,3439.26 3807.67,3417.26 3817.67,3407.26 v1(3846.67,3407.26)
$1N19697: D5.1 R6.1 R10.2 | length 86.8
  Top Layer w4: D5.1@3513.5,3795.63 3513.83,3795.96 R10.2@3513.83,3839.92
  Top Layer w8: R6.1@3471.5,3840.13 3513.61,3840.13 R10.2@3513.83,3839.92
$1N22582: C9.2 U2.1 U2.6 | length 241.5
  Top Layer w8: v1(3832.5,3708.13) 3833.03,3708.67 U2.1@3833.03,3735.05 ; U2.6@3919.74,3782.13 U2.6@3919.59,3782.29 3946.34,3782.29 v1(3946.5,3782.13) 3947.5,3781.13 C9.2@3977.49,3781.13
  Bottom Layer w8: v1(3832.5,3708.13) 3832.5,3727.13 3854.5,3749.13 3903.5,3749.13 3936.5,3782.13 v1(3946.5,3782.13)
$1N26471: D7.2 L6.2 U6.1 | length 331.7
  Bottom Layer w18: D7.2@3941.5,3389.33 3941.5,3408.13 3966.5,3433.13 4068.5,3433.13 4095.32,3406.31 L6.2@4095.32,3363.54 4095.32,3279.74 U6.1@4103.12,3271.94
$2N1192: R17.1 U3.64 | length 63.9
  Top Layer w5: U3.64@4376.63,3429.62 4376.63,3380 4377.5,3379.13 R17.1@4377.5,3366.13
$2N2812: R22.2 U3.25 | length 68.8
  Top Layer w4: R22.2@4016.5,3722.14 4084.12,3722.14 U3.25@4084.99,3721.26
$2N5115: C10.1 U3.48 | length 72.3
  Top Layer w4: C10.1@4132.5,3367.13 4132.5,3389.13 4156.15,3412.78 U3.48@4156.15,3429.62
$2N5329: C11.1 U3.50 | length 65.9
  Top Layer w4: C11.1@4175.5,3367.13 4175.5,3382.13 4183.71,3390.34 U3.50@4183.71,3429.62
$2N8130: CARD1.5 D10.1 R42.2 | length 106.2
  Top Layer w5: R42.2@4616.5,3571.14 4614.9,3569.53 D10.1@4614.9,3530.13 4615.3,3530.53 CARD1.5@4679.3,3530.53
$2N10833: R15.2 U4.C1 | length 53
  Bottom Layer w6: U4.C1@4772.85,3360.88 4776.36,3364.38 R15.2@4776.36,3412.46
$2N10977: C13.2 R15.1 | length 41.8
  Bottom Layer w6: R15.1@4776.36,3448.46 C13.2@4776.36,3490.3
$2N11171: R14.2 U4.A1 | length 52.3
  Bottom Layer w6: R14.2@4731.04,3412.46 4732.85,3410.65 U4.A1@4732.85,3360.88
$2N11292: C12.2 R14.1 | length 41.8
  Bottom Layer w6: R14.1@4731.04,3448.46 C12.2@4731.05,3490.3
$2N11927: C14.2 L5.2 U4.B1 U4.B2 U4.C2 | length 190.5
  Bottom Layer w6: L5.2@4826.85,3388.32 4882.88,3388.32 C14.2@4884.85,3386.35
  Bottom Layer w8: U4.B2@4752.85,3340.88 4757.07,3340.88 ; U4.B1@4752.85,3360.88 4752.85,3345.1 4757.07,3340.88 ; L5.2@4826.85,3388.32 4827.5,3387.67 4827.5,3362.13 4806.24,3340.88 U4.C2@4772.85,3340.88 4757.07,3340.88
$2N24050: LED1.1 R25.1 | length 59.3
  Top Layer w5: R25.1@4904.5,3273.14 4913.5,3282.13 LED1.1@4913.5,3328.67
$2N27507: LED2.2 R26.1 | length 71.4
  Top Layer w6: LED2.2@3411.5,3176.13 3412.5,3177.13 R26.1@3412.5,3247.13
$3N3720: C25.1 U5.26 | length 74.6
  Top Layer w8: C25.1@3633.95,3735.71 3633.95,3697.68 v1(3638.5,3693.13)
  Bottom Layer w8: v1(3638.5,3693.13) 3644.63,3699.26 U5.26@3644.63,3720.73
$3N3721: C26.1 U5.21 | length 75.9
  Top Layer w8: C26.1@3708.95,3735.71 3708.95,3727.68 v1(3737.5,3699.13)
  Bottom Layer w4: U5.21@3723.37,3720.73 3723.37,3713.26 v1(3737.5,3699.13)
$3N3722: C23.1 U5.2 | length 120.1
  Top Layer w8: C23.1@3557.85,3876.98 3557.85,3883.49 3581.5,3907.13 v1(3581.5,3949.13)
  Bottom Layer w8: v1(3581.5,3949.13) 3597.38,3933.25 U5.2@3597.38,3917.53
$3N3723: C24.1 U5.38 | length 71.5
  Bottom Layer w8: C24.1@3483.46,3856.36 3485.6,3858.5 U5.38@3554.1,3858.5
$3N3727: C27.1 C28.1 C29.1 U5.1 U5.22 U5.28 U5.36 | length 815.8
  Top Layer w8: v1(3478.5,3755.13) 3486.5,3763.13 3524.5,3763.13 3536.5,3775.13 ; v1(3562.5,3918.13) 3552.5,3918.13 3536.5,3902.13 3536.5,3775.13 ; C29.1@3594.67,3735.24 3594.67,3709.96 v1(3612.5,3692.13) 3595.5,3675.13 3567.5,3675.13 3536.5,3706.13 3536.5,3775.13 ; C28.1@3671.95,3735.71 3675.5,3732.16 3675.5,3711.13 3694.38,3692.25 v1(3707.62,3692.25)
  Mid-Layer 2 w8: v1(3612.5,3692.13) 3612.5,3693.13 3634.5,3715.13 3684.74,3715.13 v1(3707.62,3692.25)
  Bottom Layer w8: v1(3478.5,3755.13) 3483.49,3760.13 C27.1@3483.49,3780.13 3497.49,3794.13 3500.5,3794.13 3533.37,3827 U5.36@3554.1,3827 ; v1(3562.5,3918.13) 3563.1,3917.53 U5.1@3581.63,3917.53 ; v1(3612.5,3692.13) 3613.13,3692.76 U5.28@3613.13,3720.73 ; v1(3707.62,3692.25) U5.22@3707.62,3720.73
$3N3728: C19.2 R19.1 U5.40 | length 109.1
  Bottom Layer w8: 3524.5,3892.13 ccw(c3554.1,4096.74) U5.40@3554.1,3890
  Bottom Layer w20: R19.1@3445.25,3893.8 3483.33,3893.8 C19.2@3483.64,3893.48 cw(c3483.64,3274.31) 3524.5,3892.13
$3N3729: C20.2 JP1.1 R19.2 | length 185.7
  Bottom Layer w20: JP1.1@3226.51,3870.13 cw(c3370.64,3455.75) C20.2@3370.64,3894.48 3408.56,3894.48 R19.2@3409.25,3893.8
AP_WAKE_BT: R21.1 U5.5 | length 103.7
  Top Layer w4: v1(3655.5,3964.13) 3655.5,3934.14 R21.1@3671.5,3918.14
  Bottom Layer w4: U5.5@3644.63,3917.53 3644.63,3938.26 3655.5,3949.13 v1(3655.5,3964.13)
BT_RSTN: U3.27 U5.23 | length 460.9
  Top Layer w4: v1(3726.5,3677.13) 3731.5,3672.13 3769.5,3672.13 3788.5,3691.13 3844.5,3691.13 3851.5,3698.13 3904.5,3698.13 3922.5,3680.13 4051.5,3680.13 4065.07,3693.7 U3.27@4084.99,3693.7
  Bottom Layer w4: U5.23@3691.87,3720.73 3691.87,3685.76 3704.5,3673.13 3722.5,3673.13 v1(3726.5,3677.13)
BT_WAKE_AP: R20.1 U5.6 | length 84.4
  Top Layer w4: v1(3681.5,3964.13) 3686.5,3959.14 R20.1@3708.5,3959.14
  Bottom Layer w4: U5.6@3660.37,3917.53 3660.37,3937 3681.5,3958.13 v1(3681.5,3964.13)
CSI_CKN: FPC1.12 U3.73 | length 602.6
  Top Layer w5: U3.73@4434.01,3542.12 4484.51,3542.12 v1(4487.5,3539.13) ; v1(4969.5,3564.13) 4971.5,3564.13 4977,3569.63 4996,3569.63 4998.6,3567.03 FPC1.12@5016.69,3566.98
  Mid-Layer 1 w5: v1(4487.5,3539.13) 4493.5,3545.13 4731.06,3545.13 4756.06,3570.13 4963.5,3570.13 v1(4969.5,3564.13)
CSI_CKP: FPC1.11 U3.74 | length 605.5
  Top Layer w5: U3.74@4434.01,3555.9 4481.27,3555.9 v1(4487.5,3562.13) ; v1(4969.5,3586.13) 4970.5,3586.13 4976,3580.63 4998,3580.63 5004,3586.63 FPC1.11@5016.7,3586.63
  Mid-Layer 1 w5: v1(4487.5,3562.13) 4487.5,3561.13 4492.5,3556.13 4726.5,3556.13 4751.5,3581.13 4964.5,3581.13 v1(4969.5,3586.13)
CSI_D0N: FPC1.15 U3.69 | length 677.3
  Top Layer w5: U3.69@4434.01,3487 4472.63,3487 v1(4474.5,3485.13) ; v1(4952.5,3497.13) 4944.5,3505.13 4944.5,3510.13 4949.5,3515.13 4987.5,3515.13 4994.7,3507.93 FPC1.15@5016.69,3507.92
  Mid-Layer 1 w5: v1(4474.5,3485.13) 4475.5,3485.13 4483.5,3477.13 4483.5,3457.13 4495.5,3445.13 4925.5,3445.13 4943.5,3463.13 4943.5,3488.13 v1(4952.5,3497.13)
CSI_D0P: FPC1.14 U3.70 | length 682.7
  Top Layer w5: U3.70@4434.01,3500.78 4483.85,3500.78 v1(4499.5,3485.13) ; v1(4926.5,3498.13) 4935.5,3507.13 4935.5,3515.13 4945.5,3525.13 4987.5,3525.13 4990,3527.63 FPC1.14@5016.69,3527.61
  Mid-Layer 1 w5: v1(4499.5,3485.13) 4494.5,3480.13 4494.5,3462.13 4500.5,3456.13 4921.5,3456.13 4932.5,3467.13 4932.5,3492.13 v1(4926.5,3498.13)
CSI_D1N: FPC1.18 U3.72 | length 874
  Top Layer w5: v1(4405.5,3536.13) 4413.29,3528.34 U3.72@4434.01,3528.34 ; FPC1.18@5016.7,3448.83 5020,3452.13 5047.5,3452.13 v1(5049.5,3450.13)
  Mid-Layer 1 w5: v1(4405.5,3536.13) 4415.5,3526.13 4433.5,3526.13 4445.5,3514.13 4749.5,3514.13 4769.5,3534.13 5073.5,3534.13 5094.5,3513.13 5094.5,3477.13 5074.5,3457.13 5056.5,3457.13 v1(5049.5,3450.13)
CSI_D1P: FPC1.17 U3.71 | length 839.9
  Top Layer w5: v1(4405.5,3510.13) 4409.93,3514.56 U3.71@4434.01,3514.56 ; FPC1.17@5016.7,3468.53 5020.1,3465.13 5040.5,3465.13 v1(5049.5,3474.13)
  Mid-Layer 1 w5: v1(4405.5,3510.13) 4411.5,3516.13 4429.5,3516.13 4442.5,3503.13 4753.5,3503.13 4774.5,3524.13 5068.5,3524.13 5084.5,3508.13 5084.5,3481.86 5070.77,3468.13 5055.5,3468.13 v1(5049.5,3474.13)
CSI_MCLK: FPC1.9 R17.2 | length 1044.5
  Top Layer w4: R17.2@4377.5,3330.13 4383.51,3336.13 v1(4404.5,3336.13)
  Top Layer w5: FPC1.9@5016.69,3626.04 5057.6,3626.03 5081.5,3602.13 5081.5,3445.13 5056.5,3420.13 v1(5056.5,3341.13)
  Mid-Layer 1 w5: v1(4404.5,3336.13) 4422.5,3318.13 5033.5,3318.13 v1(5056.5,3341.13)
CSI_RSTN: FPC1.5 R37.2 U3.66 | length 1245.1
  Top Layer w5: U3.66@4404.18,3429.62 4404.18,3410.45 4404.5,3410.13 4404.5,3392.13 4422.5,3374.13 v1(4445.5,3374.13) ; R37.2@4958.34,3719.18 4978.45,3719.18 4992.9,3704.73 FPC1.5@5016.7,3704.73 ; FPC1.5@5017.1,3705.13 FPC1.5@5016.7,3704.73 ; v1(5137.5,3401.13) 5137.5,3640.87 5073.63,3704.73 FPC1.5@5016.7,3704.73
  Mid-Layer 1 w5: v1(4445.5,3374.13) 4446.5,3374.13 4450.5,3370.13 5107.5,3370.13 5137.5,3400.13 v1(5137.5,3401.13)
CSI_SCK: FPC1.6 R38.2 U3.68 | length 1132
  Top Layer w5: U3.68@4434.01,3473.22 4457.41,3473.22 4469.5,3461.13 4469.5,3449.13 4492.5,3426.13 v1(4500.5,3426.13) ; R38.2@4958.34,3673.5 4960.71,3671.13 4979.5,3671.13 4993.5,3685.13 FPC1.6@5016.69,3685.09 5071.5,3685.13 5123.5,3633.13 5123.5,3432.13 v1(5117.5,3426.13)
  Mid-Layer 1 w5: v1(4500.5,3426.13) 4511.5,3415.13 5064.5,3415.13 5087.5,3438.13 5105.5,3438.13 v1(5117.5,3426.13)
CSI_SDA: FPC1.7 R16.2 U3.67 | length 1101.7
  Top Layer w5: U3.67@4434.01,3459.45 4453.18,3459.45 4458.5,3454.13 4458.5,3442.13 4475.5,3425.13 v1(4475.5,3414.13) ; R16.2@4958.34,3627.81 4962.18,3627.81 4999.8,3665.43 FPC1.7@5016.69,3665.41 5071.2,3665.43 5109.5,3627.13 5109.5,3444.13 5095.5,3430.13 v1(5095.5,3417.13)
  Mid-Layer 1 w5: v1(4475.5,3414.13) 4485.5,3404.13 5082.5,3404.13 v1(5095.5,3417.13)
CTP_EINT: FPC2.2 H1.6 R30.2 U3.39 | length 2362.3
  Top Layer w5: v1(3969.5,3540.13) 3999.5,3540.13 4013.5,3526.13 4068.5,3526.13 4070.71,3528.34 U3.39@4084.99,3528.34
  Mid-Layer 2 w4: v1(3522.5,3150.13) 3516.5,3144.13 3380.5,3144.13 3356.5,3168.13 3356.5,3191.13 3371.5,3206.13 3422.5,3206.13 3453.5,3237.13 3453.5,3264.13 3483.5,3294.13 3840.5,3294.13 3927.5,3381.13 3927.5,3465.13 3922.5,3470.13 3922.5,3514.13 3948.5,3540.13 v1(3969.5,3540.13) 4033.5,3540.13 4037.5,3536.13 4142.5,3536.13 4254.5,3648.13 4254.5,3831.13 4305.5,3882.13 4536.5,3882.13 H1.6@4602.5,3948.13
  Bottom Layer w8: v1(3522.5,3150.13) 3539.5,3167.13 ; FPC2.2@3541,3235.33 3541,3168.63 3539.5,3167.13 ; R30.2@3704.5,3191.14 3703.49,3190.13 3629.5,3190.13 3606.5,3167.13 3539.5,3167.13
CTP_RST: FPC2.5 H1.7 R41.2 U3.38 | length 2197.8
  Top Layer w5: v1(3986.5,3559.13) 3997.5,3559.13 4019.29,3537.34 4063.71,3537.34 4068.49,3542.12 U3.38@4084.99,3542.12
  Mid-Layer 2 w4: v1(3372.5,3232.13) 3385.5,3219.13 3415.5,3219.13 3440.5,3244.13 3440.5,3267.13 3477.5,3304.13 3833.5,3304.13 3914.5,3385.13 3914.5,3456.13 3907.5,3463.13 3907.5,3521.13 3945.5,3559.13 v1(3986.5,3559.13) 4031.5,3559.13 4046.5,3574.13 4161.5,3574.13 4241.5,3654.13 4241.5,3838.13 4297.5,3894.13 4448.5,3894.13 H1.7@4502.5,3948.13
  Bottom Layer w8: v1(3372.5,3232.13) 3400.5,3204.13 3472.5,3204.13 3482,3213.63 FPC2.5@3482,3235.33 3482,3266.63 3515.5,3300.13 3593.5,3300.13 3621.5,3272.13 3664.5,3272.13 3698.5,3306.14 R41.2@3704.5,3306.14
CTP_SCL: FPC2.3 H1.4 R39.2 U3.41 | length 2380.2
  Top Layer w5: v1(3952.5,3490.13) 3968.5,3506.13 3990.5,3506.13 3995.85,3500.78 U3.41@4084.99,3500.78
  Mid-Layer 2 w4: v1(3446.5,3167.13) 3446.5,3183.13 3484.5,3221.13 3484.5,3250.13 3505.5,3271.13 3569.5,3271.13 3570.5,3270.13 3853.5,3270.13 3952.5,3369.13 v1(3952.5,3490.13) 3971.5,3509.13 4154.5,3509.13 4280.5,3635.13 4280.5,3814.13 4318.5,3852.13 4706.5,3852.13 H1.4@4802.5,3948.13
  Bottom Layer w8: v1(3446.5,3167.13) 3449.5,3164.13 3503.5,3164.13 3521.4,3182.03 FPC2.3@3521.4,3235.33 3521.4,3251.03 3535.5,3265.13 3571.5,3265.13 3607.5,3229.14 R39.2@3704.5,3229.14
CTP_SDA: FPC2.4 H1.5 R40.2 U3.40 | length 2422.4
  Top Layer w5: v1(3951.5,3520.13) 3994.5,3520.13 4000.07,3514.56 U3.40@4084.99,3514.56
  Mid-Layer 2 w4: v1(3373.5,3181.13) 3373.5,3186.13 3378.5,3191.13 3428.5,3191.13 3467.5,3230.13 3467.5,3259.13 3491.5,3283.13 3848.5,3283.13 3940.5,3375.13 3940.5,3475.13 3936.5,3479.13 3936.5,3505.13 v1(3951.5,3520.13) 3953.5,3522.13 4147.5,3522.13 4267.5,3642.13 4267.5,3822.13 4312.5,3867.13 4621.5,3867.13 H1.5@4702.5,3948.13
  Bottom Layer w8: v1(3373.5,3181.13) 3376.5,3184.13 3490.5,3184.13 3501.7,3195.33 FPC2.4@3501.7,3235.33 3501.7,3259.33 3526.5,3284.13 3579.5,3284.13 3613.5,3250.13 3670.5,3250.13 3688.5,3268.14 R40.2@3704.5,3268.14
DSI_CKN: MIPI_DSI.5 U3.84 | length 909.2
  Top Layer w5: MIPI_DSI.5@4388.1,3240.33 4388.1,3218.47 4384.43,3214.81 4384.43,3193.2 v1(4415.5,3162.13) ; U3.84@4434.01,3693.7 4464.93,3693.7 v1(4469.5,3689.13)
  Bottom Layer w5: v1(4415.5,3162.13) 4420,3157.63 4506.44,3157.63 4639.5,3290.69 4639.5,3558.13 4501,3696.63 4476.5,3696.63 4476.5,3696.13 v1(4469.5,3689.13)
DSI_CKP: MIPI_DSI.6 U3.85 | length 976.4
  Top Layer w5: MIPI_DSI.6@4368.5,3240.33 4368.5,3217.75 4372.02,3214.23 4372.02,3178.61 v1(4390.5,3160.13) ; U3.85@4434.01,3707.48 4461.85,3707.48 v1(4469.5,3715.13)
  Bottom Layer w5: v1(4390.5,3160.13) 4404,3146.63 4511,3146.63 4650.5,3286.13 4650.5,3562.69 4505.56,3707.63 4469.5,3707.63 v1(4469.5,3715.13)
DSI_D0N: MIPI_DSI.2 U3.80 | length 581.7
  Top Layer w5: U3.80@4434.01,3638.58 4458.05,3638.58 v1(4464.5,3632.13) ; MIPI_DSI.2@4447.2,3240.33 4447.2,3270.83 v1(4452.5,3276.13)
  Bottom Layer w5: v1(4452.5,3276.13) 4452.5,3257.13 4457.5,3252.13 4479.5,3252.13 4571.5,3344.13 4571.5,3525.13 v1(4464.5,3632.13)
DSI_D0P: MIPI_DSI.3 U3.81 | length 650.9
  Top Layer w5: MIPI_DSI.3@4427.5,3240.33 4427.5,3276.13 v1(4428.5,3277.13) ; U3.81@4434.01,3652.36 4469.27,3652.36 v1(4488.5,3633.13)
  Bottom Layer w5: v1(4428.5,3277.13) 4438.5,3267.13 4438.5,3254.13 4451.5,3241.13 4486.5,3241.13 4582.5,3337.13 4582.5,3532.13 4488.5,3626.13 v1(4488.5,3633.13)
DSI_D1N: MIPI_DSI.8 U3.82 | length 888.3
  Top Layer w5: MIPI_DSI.8@4329.1,3240.33 4329.1,3221.73 4326.5,3219.13 4326.5,3201.29 v1(4333.63,3194.15) ; v1(4405.5,3660.13) 4411.51,3666.14 U3.82@4434.01,3666.14
  Bottom Layer w5: v1(4333.63,3194.15) 4337.66,3190.13 4478.94,3190.13 4603.5,3314.69 4603.5,3546.5 4494.09,3655.91 4450.72,3655.91 4438,3668.63 4430.5,3668.63 4422,3660.13 v1(4405.5,3660.13)
DSI_D1P: MIPI_DSI.9 U3.83 | length 961.4
  Top Layer w5: MIPI_DSI.9@4309.4,3240.33 4309.4,3226.23 4315.5,3220.13 4315.5,3186.13 v1(4333.5,3168.13) ; v1(4405.5,3688.13) 4413.71,3679.92 U3.83@4434.01,3679.92
  Bottom Layer w5: v1(4333.5,3168.13) 4344.02,3178.65 4483.02,3178.65 4615.5,3311.13 4615.5,3550.06 4498.65,3666.91 4455.28,3666.91 4442.56,3679.63 4430.5,3679.63 4422,3688.13 v1(4405.5,3688.13)
DSI_PWM: R23.2 U3.86 U6.4 | length 1477.7
  Top Layer w4: v1(4410.5,3721.13) 4433.88,3721.13 U3.86@4434.01,3721.26
  Bottom Layer w4: U6.4@4012.72,3197.14 4036.92,3172.93 R23.2@4036.92,3145.53 4065.32,3117.13 4533.5,3117.13 4690.5,3274.13 4690.5,3582.13 4531.5,3741.13 4461.5,3741.13 4449.5,3729.13 4418.5,3729.13 v1(4410.5,3721.13)
  other v1: 4035.45,3174.41
DSI_RST: MIPI_DSI.18 U3.87 | length 1305.5
  Top Layer w4: MIPI_DSI.18@4132.2,3240.33 4132.2,3175.43 4155.5,3152.13 4289.5,3152.13 4304.5,3137.13 v1(4345.5,3137.13) ; U3.87@4434.01,3735.04 4434.1,3735.13 4483.5,3735.13 v1(4493.5,3725.13)
  Bottom Layer w4: v1(4345.5,3137.13) 4346.68,3137.13 4356.68,3127.13 4526.5,3127.13 4678.5,3279.13 4678.5,3577.13 4526.5,3729.13 4497.5,3729.13 v1(4493.5,3725.13)
DU0+: D2.1 U2.7 USB1.B6 | length 838.4
  Top Layer w4: U2.7@3919.59,3801.98 3948.35,3801.98 v1(3952.5,3806.13)
  Top Layer w8: USB1.B6@3405.8,3524.63 3435,3524.63 v1(3450.9,3508.74) 3467.5,3492.13 D2.1@3477.1,3492.13
  Mid-Layer 2 w4: v1(3450.9,3508.74) 3471.5,3529.34 3471.5,3690.13 3531.5,3750.13 3874.5,3750.13 3930.5,3806.13 v1(3952.5,3806.13)
DU0-: D1.1 U2.8 USB1.B7 | length 822
  Top Layer w4: U2.8@3919.59,3821.66 3962.97,3821.66 v1(3974.5,3810.13)
  Top Layer w8: USB1.B7@3405.8,3583.63 3446,3583.63 v1(3455.32,3592.95) 3477.1,3614.73 D1.1@3477.1,3616.13
  Mid-Layer 2 w4: v1(3455.32,3592.95) 3461.5,3599.13 3461.5,3696.13 3524.5,3759.13 3869.5,3759.13 3933.5,3823.13 3959.5,3823.13 3972.5,3810.13 v1(3974.5,3810.13)
GND: C1.1 C2.1 C3.1 C4.1 C5.2 C6.1 C7.1 C8.1 C9.1 C10.2 C11.2 C13.1 C14.1 C15.2 C16.2 C17.1 C18.1 C19.1 C20.1 C21.2 C22.2 C23.2 C24.2 C25.2 C26.2 C27.2 C28.2 C29.2 C30.2 C31.2 C32.1 C33.2 C34.2 C35.1 C36.1 C37.1 C38.1 C39.2 C40.1 C41.1 C42.1 C43.1 C44.1 C45.1 C46.1 C47.1 CARD1.6 CARD1.9 CARD1.10 D1.2 D2.2 D3.2 D4.2 D6.1 D8.2 D9.2 D10.2 D11.2 D12.2 D13.2 FEL1.3 FEL1.4 FPC1.8 FPC1.10 FPC1.13 FPC1.16 FPC1.19 FPC1.25 FPC1.26 FPC2.6 FPC2.7 FPC2.8 H1.1 H1.12 H2.1 JP1.2 JP1.3 MIPI_DSI.1 MIPI_DSI.4 MIPI_DSI.7 MIPI_DSI.10 MIPI_DSI.13 MIPI_DSI.15 MIPI_DSI.17 MIPI_DSI.19 MIPI_DSI.23 MIPI_DSI.25 MIPI_DSI.26 R2.2 R5.2 R9.1 R11.2 R13.2 R23.1 R24.1 R25.2 R26.2 R27.1 R32.2 RST1.1 RST1.2 U1.1 U1.4 U1.6 U1.13 U1.18 U1.25 U2.2 U2.17 U3.51 U3.89 U4.A2 U4.B3 U5.19 U5.41 U6.2 U7.4 USB1.12 USB1.13 USB1.14 USB1.15 USB1.A1B12 USB1.B1A12 X1.2 X1.4 X2.2 X2.4 | length 7123.5
  Top Layer w4: v1(3845.5,3812.13) 3852.72,3804.92 U2.2@3852.72,3735.05 ; U3.51@4197.49,3429.62 v1(4197.49,3453.12) ; v1(4316.5,3339.13) 4321.51,3339.13 C45.1@4333.5,3327.14
  Top Layer w5: FEL1.3@3165.8,3184.83 v1(3199.94,3184.83) FEL1.4@3331.2,3184.83 ; C21.2@3556.67,3775.24 v1(3594.67,3775.24) ; C23.2@3557.85,3836.98 3592.84,3836.98 3601.64,3836.99 3615.65,3822.99 v1(3630.85,3822.99) ; C17.1@4186.3,3877.05 v1(4206.02,3877.05) 4224.15,3877.05 C18.1@4224.43,3877.33 ; MIPI_DSI.4@4407.8,3240.33 v1(4407.8,3208.83) v1@4408.5,3208.13 ; MIPI_DSI.1@4466.9,3240.33 4466.9,3209.73 v1(4467.5,3209.13) ; v1(4978.5,3438.13) 4987.4,3429.23 FPC1.19@5016.69,3429.18 ; v1(4978.5,3477.13) 4989.6,3488.23 FPC1.16@5016.69,3488.24 ; FPC1.13@5016.69,3547.29 5045.7,3547.33 v1(5050.5,3552.13) ; FPC1.10@5016.7,3606.33 5048.3,3606.33 v1(5048.5,3606.13) ; FPC1.8@5017.1,3646.13 FPC1.8@5016.69,3645.72 5048.1,3645.73 v1(5048.5,3646.13)
  Top Layer w6: v1(3552.5,3468.13) 3553.5,3469.13 R27.1@3553.5,3486.13 ; v1(3710.5,3877.14) 3713.5,3877.14 C41.1@3753.5,3837.14 ; H1.12@4002.5,3948.13 4002.5,3908.13 4018.5,3892.13 4076.49,3892.13 C40.1@4091.5,3877.13 ; C38.1@4049.5,3327.14 C37.1@4090.5,3327.14 ; C11.2@4175.5,3327.13 C44.1@4219.5,3327.14 ; v1(4579.5,3730.13) 4582.44,3727.19 D13.2@4582.44,3704.21 D12.2@4582.44,3658.84 D11.2@4582.44,3613.47 ; D10.2@4582.1,3530.13 4603.1,3509.13 4663.42,3509.13 CARD1.6@4685.32,3487.23 ; D8.2@4582.44,3401.36 4603.22,3422.13 4607.04,3422.13 ; D9.2@4582.44,3446.73 4607.04,3422.13 ; 4723.5,3434.41 4711.22,3422.13 4607.04,3422.13
  Top Layer w7: C3.1@3484.5,3434.66 v1(3509.9,3460.06) D2.2@3509.9,3492.13 D3.2@3509.9,3533.13 D4.2@3509.9,3574.13 ; D1.2@3509.9,3616.13 D4.2@3509.9,3574.13 ; C4.1@3558.67,3567.75 3552.29,3574.13 v1(3530.37,3574.13) D4.2@3509.9,3574.13 ; v1(4467.5,3209.13) 4467.5,3180.73 MIPI_DSI.26@4506.3,3141.93
  Top Layer w8: USB1.13@3369.8,3384.03 3366.5,3387.33 3366.5,3410.13 3383.5,3427.13 USB1.B1A12@3405.8,3427.13 ; USB1.12@3369.8,3724.23 3369.8,3717.13 USB1.A1B12@3405.8,3681.13 ; v1(3974.5,3174.13) 3993.5,3193.13 4021.5,3193.13 4033.8,3205.43 MIPI_DSI.23@4033.8,3240.33 ; MIPI_DSI.17@4151.9,3240.33 4151.9,3186.53 v1(4151.5,3186.13) 4169.5,3168.13 4185.5,3168.13 4197.5,3180.13 4197.5,3195.13 4191.3,3201.33 MIPI_DSI.15@4191.3,3240.33 4191.3,3260.93 4199.5,3269.13 4222.5,3269.13 ; MIPI_DSI.13@4230.7,3240.33 4230.7,3260.93 4222.5,3269.13 ; MIPI_DSI.10@4289.7,3240.33 4289.5,3240.53 4289.5,3264.13 4284.5,3269.13 ; MIPI_DSI.7@4348.8,3240.33 4348.5,3240.63 4348.5,3262.13 4341.5,3269.13 ; MIPI_DSI.4@4407.8,3240.33 4406.5,3241.63 4406.5,3265.13 4402.5,3269.13 4341.5,3269.13 ; 4222.5,3269.13 4284.5,3269.13 ; 4284.5,3269.13 4341.5,3269.13
  Top Layer w9: C37.1@4090.5,3327.14 C10.2@4132.5,3327.13
  Top Layer w10: RST1.2@3163.8,3823.83 3163.8,3770.83 v1(3165.5,3769.13) ; RST1.1@3329.2,3823.83 3329.2,3856.45 v1(3338.88,3866.13) ; C5.2@3376.5,3868.13 3402.5,3868.13 v1(3408.5,3862.13) ; v1(3385.5,3300.13) 3401.5,3284.13 3453.97,3284.13 C2.1@3484.5,3253.61 ; v1(3552.5,3468.13) 3552.67,3467.97 C33.2@3552.67,3443.26 v1(3528.5,3419.09) 3528.5,3378.42 C34.2@3553.67,3353.26 ; v1(3702.67,3363.26) 3684.46,3345.05 U1.13@3684.46,3321.99 3683.67,3321.2 3683.67,3262.26 R2.2@3704.67,3241.25 ; v1(3702.67,3431.26) 3684.46,3449.47 U1.6@3684.46,3472.51 3684.46,3503.47 3681.32,3506.61 3681.32,3536.91 R5.2@3703.67,3559.26 ; U1.4@3723.83,3472.51 3723.83,3441.09 v1(3733.67,3431.26) ; R13.2@3762.67,3241.25 3771.67,3241.25 3782.88,3252.47 U1.18@3782.88,3321.99 3782.88,3347.05 v1(3766.67,3363.26) ; R11.2@3763.67,3559.26 3774.67,3559.26 3784.67,3549.26 3784.67,3474.3 U1.1@3782.88,3472.51 3782.88,3447.47 v1(3766.67,3431.26) ; v1(3906.5,3272.13) 3909.67,3268.96 C8.1@3909.67,3234.78 ; R9.1@3915.67,3397.25 3917.67,3399.25 C7.1@3917.67,3435.26 3917.67,3461.97 3916.5,3463.13 ; C6.1@3916.05,3574.13 C6.1@3909.67,3567.75 3936.12,3567.75 v1(3942.5,3574.13) ; MIPI_DSI.23@4033.8,3240.33 4033.8,3265.43 4041.5,3273.13 4099.5,3273.13 4112.5,3260.13 4112.5,3240.43 MIPI_DSI.19@4112.6,3240.33 ; v1(4132.5,3306.13) C10.2@4132.5,3327.13 ; v1(4175.5,3305.13) C11.2@4175.5,3327.13 ; v1(4476.5,3765.13) 4509.51,3798.14 C39.2@4509.51,3801.13 ; CARD1.6@4679.3,3487.23 4685.32,3487.23 4710.4,3487.23 4723.5,3474.13 4723.5,3434.41 4723.5,3350.52 v1(4713.85,3340.88) ; CARD1.10@4748.2,3768.73 4748.2,3723.43 v1(4748.5,3723.13) ; R25.2@4940.5,3273.14 v1(4967.5,3273.14) ; v1(5126.5,3839.13) 5128.3,3837.33 FPC1.26@5128.3,3818.33 ; v1(5127.5,3277.13) 5128.3,3277.93 FPC1.25@5128.31,3295.91
  Top Layer w15: v1(4896.5,3763.13) C35.1@4920.51,3763.13
  Top Layer w18: v1(3974.5,3174.13) 3974.5,3142.23 MIPI_DSI.25@3974.8,3141.93
  Mid-Layer 2 w10: v1(3879.5,3811.13) 3897.5,3811.13 3925.5,3839.13 3977.5,3839.13 4006.5,3810.13 v1(4006.5,3768.13)
  Bottom Layer w4: v1(4192.5,3635.13) v1(4192.5,3661.13) 4200.5,3669.13 X1.4@4200.5,3684.05 ; C15.2@4203.57,3635.13 C15.2@4214.49,3646.05
  Bottom Layer w5: v1(3708.95,3775.71) 3720.65,3764.01 U5.19@3750.9,3764.01 ; v1(4192.5,3635.13) 4203.57,3635.13 4220.5,3635.13 4235.5,3620.13 4263.5,3620.13 4281.5,3638.13 4281.5,3693.05 4278.42,3696.13 ; C14.1@4884.85,3445.4 4873.5,3456.76 4873.5,3521.16 R32.2@4891.34,3538.99
  Bottom Layer w6: C43.1@4080.5,3645.13 4099.51,3664.13 4136.58,3664.13 C16.2@4157.5,3685.05 4157.5,3646.13 C42.1@4158.49,3645.13 ; X1.2@4250.5,3724.05 4278.42,3696.13 C36.1@4323.51,3696.13 4353.51,3726.13 4390.5,3726.13 4429.5,3765.13 v1(4429.5,3772.13) ; v1(4579.5,3730.13) 4716.5,3593.13 4749.9,3593.13 D6.1@4769.9,3573.13 ; U4.A2@4732.85,3340.88 U4.B3@4752.85,3320.88 ; C13.1@4776.36,3530.3 4798.5,3508.16 4798.5,3428.13 4811.5,3415.13 4854.58,3415.13 C14.1@4884.85,3445.4
  Bottom Layer w8: v1(3385.5,3300.13) 3400.5,3285.13 3449.5,3285.13 3462.3,3272.33 FPC2.6@3462.3,3235.33 ; C22.2@3443.46,3822.36 C24.2@3443.46,3856.36 ; v1(3942.5,3574.13) 3942.5,3576.13 3943.5,3577.13 4000.5,3577.13 4043.51,3534.13 C46.1@4043.51,3500.13 ; v1(4713.85,3340.88) U4.A2@4732.85,3340.88
  Bottom Layer w10: v1(3165.5,3769.13) 3166.49,3770.12 JP1.3@3166.49,3812.06 ; JP1.2@3166.49,3928.2 3166.49,3971.12 v1(3172.5,3977.13) ; v1(3270.5,3815.13) 3270.5,3847.13 v1(3271.5,3848.13) 3293.5,3848.13 v1(3302.5,3857.13) 3329.88,3857.13 v1(3338.88,3866.13) 3404.5,3866.13 v1(3408.5,3862.13) 3408.5,3832.13 3409.5,3831.13 ; v1(3357.5,3967.13) 3370.64,3953.99 C20.1@3370.64,3934.48 ; v1(3411.5,3930.13) 3480.29,3930.13 C19.1@3483.64,3933.48 ; C22.2@3443.46,3822.36 3418.27,3822.36 3409.5,3831.13 ; C27.2@3443.49,3780.13 3431.5,3780.13 3408.5,3803.13 3408.5,3830.13 3409.5,3831.13 ; C32.1@3940.92,3177.01 3971.62,3177.01 v1(3974.5,3174.13) 3974.5,3153.13 3984.5,3143.13 3998.52,3143.13 R23.1@4000.92,3145.53 ; U6.2@4103.12,3234.54 4136.1,3234.54 4151.5,3219.13 v1(4151.5,3186.13) 4151.5,3159.13 4137.5,3145.13 4116.32,3145.13 R24.1@4115.92,3145.54 ; v1(4978.5,3438.13) v1(4978.5,3477.13) 4978.5,3529.13 5001.5,3552.13 v1(5050.5,3552.13) 5050.5,3604.13 v1(5048.5,3606.13) v1(5048.5,3646.13)
  other v1: 3733.5,3127.13 3210,3162.14 4610,3162.14 4750,3162.14 3331.5,3230.13 3140,3232.14 3210,3232.14 5030,3232.14 5100,3232.14 3140,3302.14 3210,3302.14 3280,3302.14 3350,3302.14 3910,3302.14 4960,3302.14 5030,3302.14 4443.5,3342.13 3440.5,3361.13 3733.67,3363.26 3140,3372.14 3702.67,3397.26 3733.67,3397.26 3766.67,3397.26 3140,3442.14 3210,3442.14 3210,3512.14 4337.5,3513.13 3882.5,3516.13 4324.5,3537.13 4350.5,3537.13 3210,3582.14 4170.5,3615.13 3210,3652.14 3280,3652.14 3140,3722.14 3280,3722.14 4820,3722.14 5100,3722.14 3133.5,3767.13 3189.5,3771.13 3845.5,3774.13 3633.5,3776.13 3671.95,3775.71 3358.5,3779.13 3280,3792.14 3862.51,3792.13 4680,3792.14 4820,3792.14 4890,3792.14 5100,3792.14 3374.5,3807.83 3374.5,3839.13 3140,3862.14 4750,3862.14 4890,3862.14 4960,3862.14 5030,3862.14 5100,3862.14 3670.85,3872.99 3249.5,3926.13 4050,3932.14 4750,3932.14 3327.5,3937.13 3293.5,3948.13 3259.5,3952.13 3409.5,3954.13 3322.5,3967.13 3390.5,3970.13 3292.5,3975.13 3212.5,3976.13 3248.5,3977.13 3137.5,3978.13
